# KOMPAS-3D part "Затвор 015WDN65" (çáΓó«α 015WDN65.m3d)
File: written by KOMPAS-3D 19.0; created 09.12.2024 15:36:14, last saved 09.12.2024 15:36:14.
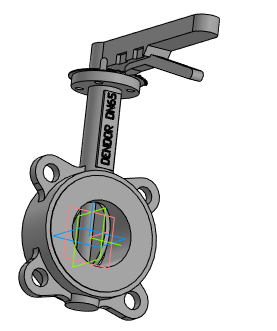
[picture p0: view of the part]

Document properties: Автор: Евгений; Полное имя файла: ..\Затвор 015WDN65.a3d

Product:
- Part/product: Затвор 015WDN65
    Масса: 5.44238

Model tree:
1. Операция без истории:1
